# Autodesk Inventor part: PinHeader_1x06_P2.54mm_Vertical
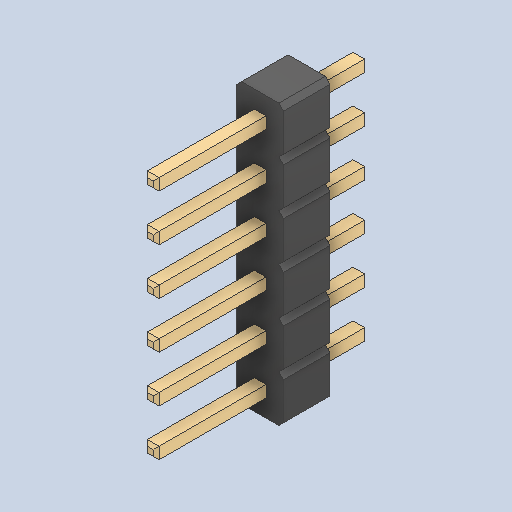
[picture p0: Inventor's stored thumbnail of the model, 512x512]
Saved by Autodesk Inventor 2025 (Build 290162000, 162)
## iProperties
Created: 2026-09
Part Number: PinHeader_1x06_P2.54mm_Vertical
Material: Generic
Document SubType Name: Modeling
Designer: Leonardo
Density: 1 g/cm^3
Appearance: Default
Author: Leonardo
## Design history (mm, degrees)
feature "Base1"
body "Solid1"
